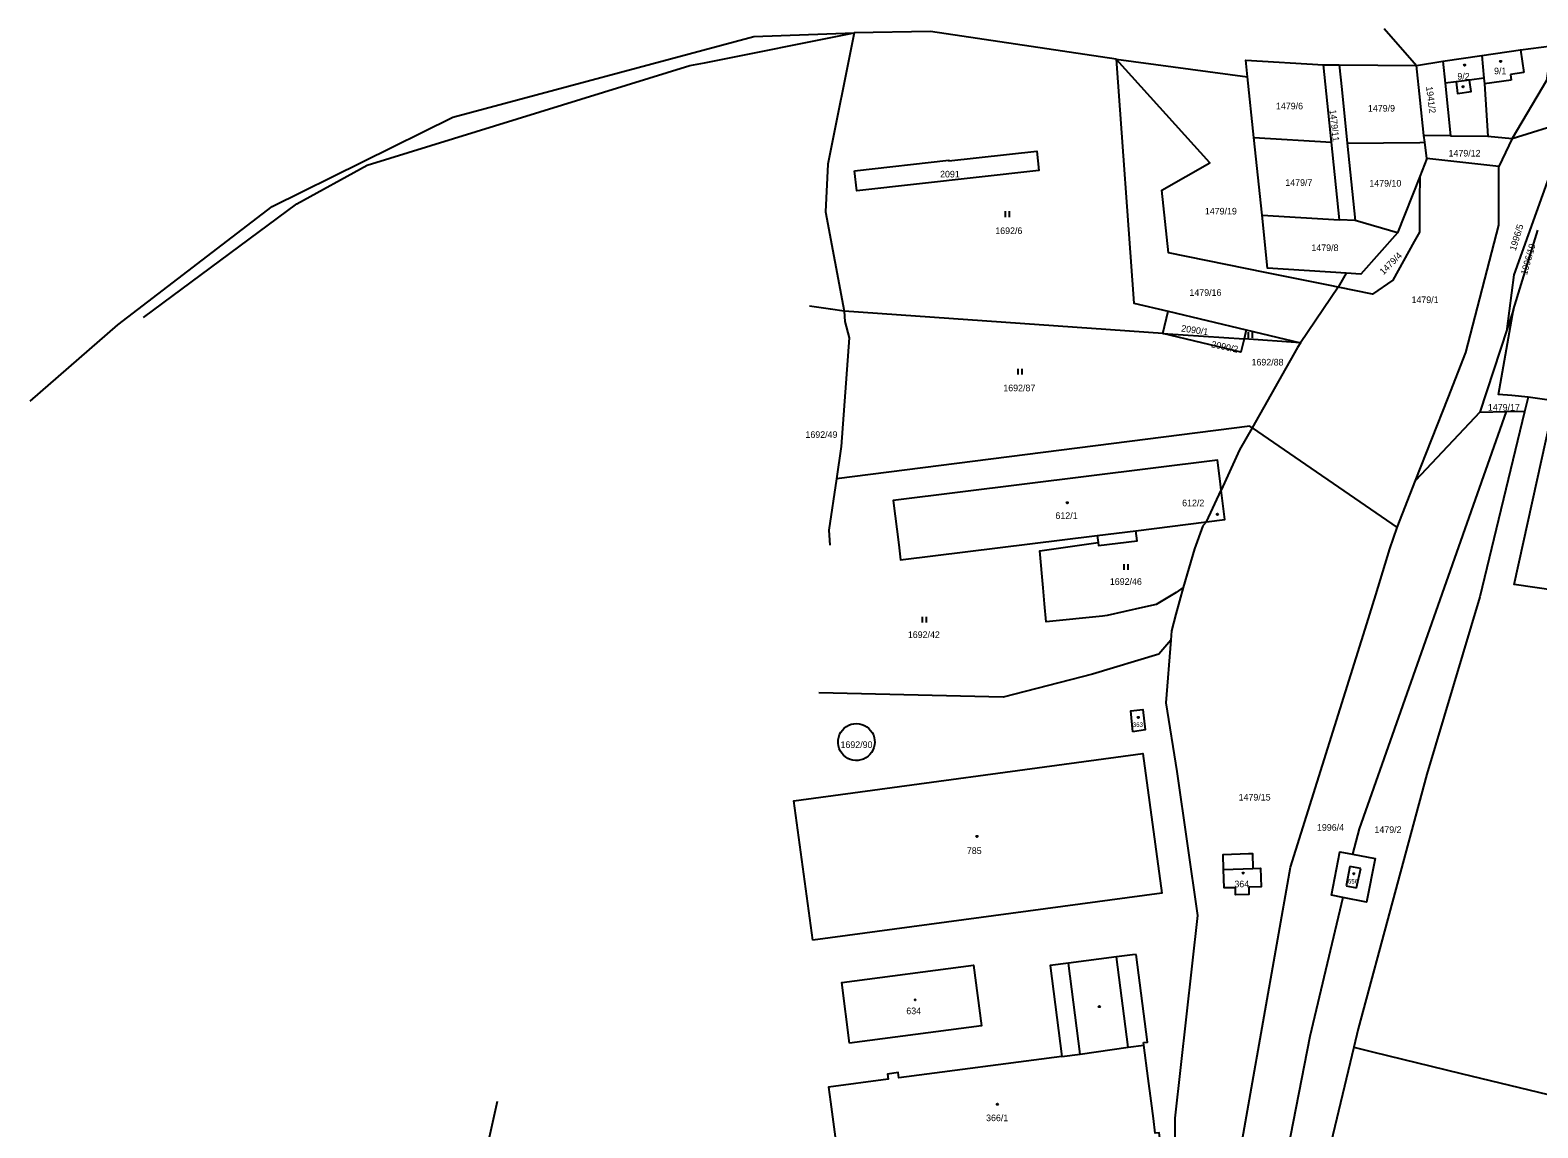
# Model space of a CAD drawing. Extents: x -794765 to -785424, y -1118958 to -1108731.
# Drawn here: x -788665.5 to -788278.3, y -1117100.4 to -1116818.5 of the extents above; entities that cross this region are included whole.
import ezdxf

# ---------------------------------------------------------------- set-up
doc = ezdxf.new("R2010")
doc.units = 0
for name, color, linetype in [('Level 66', 7, 'Continuous'), ('Level 75', 7, 'Continuous'), ('Level 76', 7, 'Continuous'), ('Level 77', 7, 'Continuous'), ('Level 79', 7, 'Continuous')]:
    doc.layers.add(name, color=color, linetype=linetype)

msp = doc.modelspace()

# ---------------------------------------------------------------- linework, layer by layer
at = {"layer": 'Level 66'}
for p, q in [((-788415, -1116866.49), (-788415, -1116864.99)), ((-788414, -1116866.49), (-788414, -1116864.99)), ((-788352.63, -1116897.53), (-788352.63, -1116896.03)), ((-788351.63, -1116897.53), (-788351.63, -1116896.03)), ((-788411.76, -1116906.96), (-788411.76, -1116905.46)), ((-788410.76, -1116906.96), (-788410.76, -1116905.46)), ((-788384.55, -1116957.13), (-788384.55, -1116955.63)), ((-788383.55, -1116957.13), (-788383.55, -1116955.63)), ((-788436.36, -1116970.63), (-788436.36, -1116969.13)), ((-788435.36, -1116970.63), (-788435.36, -1116969.13))]:
    msp.add_line(p, q, dxfattribs=at)
at = {"layer": 'Level 75'}
for p, q in [((-788317.76, -1116818.05), (-788309.48, -1116827.52)), ((-788302.69, -1116826.4), (-788292.73, -1116825.02)), ((-788386.63, -1116825.89), (-788352.86, -1116830.46)), ((-788333.34, -1116827.34), (-788329.35, -1116827.41)), ((-788331.29, -1116847.25), (-788333.34, -1116827.34)), ((-788329.35, -1116827.41), (-788309.48, -1116827.52)), ((-788309.48, -1116827.52), (-788302.69, -1116826.4)), ((-788351.23, -1116846.07), (-788352.86, -1116830.46)), ((-788284.93, -1116846.27), (-788270.62, -1116841.89)), ((-788349.15, -1116865.96), (-788351.23, -1116846.07)), ((-788351.23, -1116846.07), (-788331.29, -1116847.25)), ((-788329.24, -1116867.16), (-788331.29, -1116847.25)), ((-788327.32, -1116847.46), (-788325.2, -1116867.4)), ((-788307.37, -1116847.28), (-788307.58, -1116845.56)), ((-788300.73, -1116845.61), (-788307.58, -1116845.56)), ((-788306.86, -1116851.48), (-788307.37, -1116847.28)), ((-788300.73, -1116845.61), (-788291.15, -1116845.67)), ((-788291.15, -1116845.67), (-788284.93, -1116846.27)), ((-788284.93, -1116846.27), (-788288.33, -1116853.47)), ((-788306.86, -1116851.48), (-788308.66, -1116856.04)), ((-788288.33, -1116853.47), (-788306.86, -1116851.48)), ((-788308.66, -1116856.04), (-788314.38, -1116870.56)), ((-788349.15, -1116865.96), (-788329.24, -1116867.16)), ((-788325.2, -1116867.4), (-788329.24, -1116867.16)), ((-788314.38, -1116870.56), (-788325.2, -1116867.4)), ((-788284.57, -1116890.25), (-788278.3, -1116869.83)), ((-788327.57, -1116880.91), (-788329.59, -1116884.53)), ((-788329.59, -1116884.53), (-788339.25, -1116898.78)), ((-788374.64, -1116896.38), (-788456.49, -1116890.68)), ((-788374.64, -1116896.38), (-788373.27, -1116890.69)), ((-788373.27, -1116890.69), (-788353.2, -1116895.49)), ((-788284.57, -1116890.25), (-788286.19, -1116895.2)), ((-788374.64, -1116896.38), (-788353.75, -1116897.78)), ((-788353.2, -1116895.49), (-788353.75, -1116897.78)), ((-788339.25, -1116898.78), (-788353.75, -1116897.78)), ((-788353.2, -1116895.49), (-788339.25, -1116898.78)), ((-788339.25, -1116898.78), (-788340.06, -1116899.97)), ((-788286.19, -1116895.2), (-788293.21, -1116916.58)), ((-788340.06, -1116899.97), (-788351.7, -1116920.59)), ((-788280.81, -1116912.75), (-788281.72, -1116916.5)), ((-788219.76, -1116921.65), (-788280.81, -1116912.75)), ((-788293.21, -1116916.58), (-788309.73, -1116934.13)), ((-788293.21, -1116916.58), (-788286.44, -1116916.39)), ((-788281.72, -1116916.5), (-788286.44, -1116916.39)), ((-788351.7, -1116920.59), (-788314.48, -1116946.2)), ((-788363.42, -1116944.78), (-788359.67, -1116936.61)), ((-788359.67, -1116936.61), (-788359.89, -1116934.35)), ((-788314.48, -1116946.2), (-788309.73, -1116934.13)), ((-788381.59, -1116947.04), (-788363.42, -1116944.78)), ((-788363.42, -1116944.78), (-788364.33, -1116945.8)), ((-788369.37, -1116961.66), (-788371.22, -1116962.92)), ((-788322.23, -1116970.93), (-788319.9, -1116963.51)), ((-788325.58, -1117079.7), (-788320.78, -1117080.88))]:
    msp.add_line(p, q, dxfattribs=at)
for points in [[(-788665.52, -1116913.8), (-788643.02, -1116894.19), (-788603.36, -1116863.8), (-788557.01, -1116840.86), (-788479.67, -1116820.14), (-788453.87, -1116819.18)], [(-788636.39, -1116892.24), (-788597.01, -1116863.09), (-788578.99, -1116853.18), (-788496.14, -1116827.56), (-788492.3, -1116826.88), (-788453.87, -1116819.18)], [(-788453.87, -1116819.18), (-788460.63, -1116852.93), (-788461.23, -1116865.16), (-788456.49, -1116890.68)], [(-788386.63, -1116825.89), (-788434.34, -1116818.85), (-788453.87, -1116819.18)], [(-788292.73, -1116825.02), (-788282.75, -1116823.53), (-788274.84, -1116822.53), (-788276.12, -1116831.38), (-788284.93, -1116846.27)], [(-788292.73, -1116825.02), (-788292.17, -1116830.8), (-788292.03, -1116832.27), (-788291.15, -1116845.67)], [(-788329.59, -1116884.53), (-788331.7, -1116884.1), (-788348.34, -1116880.7), (-788373.2, -1116875.63), (-788374.9, -1116859.6), (-788362.54, -1116852.57), (-788386.63, -1116825.89)], [(-788386.63, -1116825.89), (-788382.08, -1116888.59), (-788373.27, -1116890.69)], [(-788352.86, -1116830.46), (-788353.31, -1116826.18), (-788333.34, -1116827.34)], [(-788329.35, -1116827.41), (-788328.7, -1116833.74), (-788327.32, -1116847.46)], [(-788307.58, -1116845.56), (-788308.53, -1116836.47), (-788309.48, -1116827.52)], [(-788302.69, -1116826.4), (-788302.1, -1116832.09), (-788300.73, -1116845.61)], [(-788327.32, -1116847.46), (-788308.6, -1116847.29), (-788307.37, -1116847.28)], [(-788453.84, -1116854.6), (-788429.6, -1116851.89), (-788429.57, -1116852.08), (-788407, -1116849.56), (-788406.45, -1116854.49), (-788453.23, -1116859.75), (-788453.84, -1116854.6)], [(-788286.19, -1116895.2), (-788284.39, -1116881.3), (-788274.95, -1116855.05), (-788273.57, -1116849.78)], [(-788308.66, -1116856.04), (-788308.7, -1116862.07), (-788308.75, -1116870.35), (-788310.09, -1116872.78), (-788315.56, -1116882.7), (-788320.81, -1116886.33), (-788329.59, -1116884.53)], [(-788309.73, -1116934.13), (-788301.38, -1116912.93), (-788296.79, -1116901.27), (-788288.35, -1116868.54), (-788288.33, -1116853.47)], [(-788327.57, -1116880.91), (-788347.72, -1116879.64), (-788349.15, -1116865.96)], [(-788314.38, -1116870.56), (-788323.78, -1116881.15), (-788327.57, -1116880.91)], [(-788456.49, -1116890.68), (-788459.97, -1116890.16), (-788465.34, -1116889.35)], [(-788456.49, -1116890.68), (-788456.26, -1116893.3), (-788455.22, -1116897.54), (-788457.2, -1116925.38), (-788458.45, -1116933.71)], [(-788280.81, -1116912.75), (-788285.02, -1116912.36), (-788288.45, -1116912.04), (-788284.57, -1116890.25)], [(-788353.75, -1116897.78), (-788354.57, -1116901.2), (-788374.64, -1116896.38)], [(-788286.44, -1116916.39), (-788324.23, -1117023.59), (-788325.92, -1117030.13)], [(-788281.72, -1116916.5), (-788293.19, -1116964.03), (-788306.8, -1117009.56), (-788324.46, -1117075.03), (-788325.58, -1117079.7)], [(-788160.99, -1116937.11), (-788164.62, -1116978.28), (-788284.44, -1116960.86), (-788274.96, -1116918.14), (-788160.99, -1116937.11)], [(-788351.7, -1116920.59), (-788352.26, -1116920.2), (-788458.45, -1116933.71)], [(-788351.7, -1116920.59), (-788354.93, -1116926.31), (-788359.67, -1116936.61)], [(-788359.89, -1116934.35), (-788360.63, -1116928.9), (-788443.88, -1116939.25), (-788442.46, -1116950.69), (-788441.98, -1116954.55), (-788391.49, -1116948.28), (-788391.25, -1116950.11)], [(-788458.45, -1116933.71), (-788460.41, -1116946.93), (-788460.16, -1116950.78)], [(-788363.42, -1116944.78), (-788358.72, -1116944.2), (-788359.67, -1116936.61)], [(-788391.25, -1116950.11), (-788391.16, -1116950.84), (-788381.24, -1116949.67), (-788381.59, -1116947.04)], [(-788364.33, -1116945.8), (-788366.46, -1116951.67), (-788369.37, -1116961.66)], [(-788319.9, -1116963.51), (-788316.32, -1116951.73), (-788314.48, -1116946.2)], [(-788371.22, -1116962.92), (-788376.33, -1116965.98), (-788379.87, -1116966.79), (-788388.94, -1116968.86), (-788390.17, -1116968.99), (-788404.59, -1116970.47), (-788405.01, -1116965.84), (-788405.39, -1116961.7), (-788406.26, -1116952.23), (-788391.25, -1116950.11)], [(-788369.37, -1116961.66), (-788371.29, -1116968.5), (-788372.43, -1116972.75), (-788372.61, -1116975.15)], [(-788355.85, -1117112.97), (-788341.83, -1117033.48), (-788322.23, -1116970.93)], [(-788372.61, -1116975.15), (-788375.62, -1116978.8), (-788392.69, -1116983.89), (-788415.6, -1116989.83), (-788462.96, -1116988.72)], [(-788372.61, -1116975.15), (-788373.83, -1116991.28), (-788371.03, -1117008.88), (-788365.73, -1117045.9), (-788371.59, -1117097.93), (-788371.59, -1117130.38)], [(-788382.31, -1116998.67), (-788382.89, -1116993.35), (-788379.75, -1116993), (-788379.15, -1116998.2), (-788382.31, -1116998.67)], [(-788453.55, -1117006.07), (-788454.23, -1117005.98), (-788454.9, -1117005.8), (-788455.53, -1117005.52), (-788456.11, -1117005.15), (-788456.64, -1117004.7), (-788457.09, -1117004.19), (-788457.46, -1117003.61), (-788457.75, -1117002.98), (-788457.94, -1117002.32), (-788458.03, -1117001.63), (-788458.04, -1117001.44), (-788458.01, -1117000.75), (-788457.88, -1117000.07), (-788457.65, -1116999.42), (-788457.32, -1116998.81), (-788456.92, -1116998.26), (-788456.44, -1116997.76), (-788455.89, -1116997.35), (-788455.28, -1116997.01), (-788454.64, -1116996.77), (-788453.96, -1116996.62), (-788453.28, -1116996.58), (-788452.59, -1116996.63), (-788451.92, -1116996.79), (-788451.28, -1116997.05), (-788450.68, -1116997.39), (-788450.14, -1116997.82), (-788449.67, -1116998.33), (-788449.28, -1116998.89), (-788448.97, -1116999.51), (-788448.75, -1117000.16), (-788448.64, -1117000.84), (-788448.61, -1117001.38), (-788448.67, -1117002.07), (-788448.83, -1117002.74), (-788449.08, -1117003.38), (-788449.42, -1117003.98), (-788449.85, -1117004.52), (-788450.35, -1117005), (-788450.91, -1117005.39), (-788451.53, -1117005.71), (-788452.18, -1117005.92), (-788452.86, -1117006.05), (-788453.55, -1117006.07)], [(-788464.56, -1117052.22), (-788469.36, -1117016.4), (-788379.74, -1117004.31), (-788374.89, -1117040.12), (-788464.56, -1117052.22)], [(-788352.62, -1117029.97), (-788351.62, -1117029.93), (-788351.49, -1117033.84), (-788349.54, -1117033.77), (-788349.37, -1117038.53), (-788352.58, -1117038.63), (-788352.52, -1117040.48), (-788355.95, -1117040.59), (-788356.01, -1117038.75), (-788358.88, -1117038.81), (-788359.07, -1117034.11), (-788359.18, -1117030.18), (-788352.62, -1117029.97)], [(-788328.38, -1117041.28), (-788331.35, -1117040.69), (-788329.18, -1117029.51), (-788325.92, -1117030.13)], [(-788325.92, -1117030.13), (-788320.09, -1117031.26), (-788322.36, -1117042.47), (-788328.38, -1117041.28)], [(-788328.38, -1117041.28), (-788336.86, -1117076.93), (-788352.61, -1117157.66), (-788354, -1117175.83)], [(-788381.44, -1117055.88), (-788382.45, -1117056.02), (-788386.52, -1117056.54), (-788398.9, -1117058.14), (-788403.61, -1117058.77), (-788400.56, -1117082.11), (-788442.41, -1117087.59), (-788442.59, -1117086.26), (-788445.34, -1117086.66), (-788445.17, -1117087.95), (-788460.49, -1117089.96), (-788459.99, -1117093.74), (-788457.95, -1117109.17), (-788457.73, -1117110.81), (-788459.35, -1117111.02), (-788459.07, -1117113.15), (-788457.45, -1117112.93), (-788456.88, -1117117.22)], [(-788379.58, -1117078.54), (-788378.59, -1117078.41), (-788381.44, -1117055.88)], [(-788455.08, -1117078.71), (-788457.05, -1117063.06), (-788423.25, -1117058.65), (-788421.2, -1117074.21), (-788455.08, -1117078.71)], [(-788377.06, -1117098.05), (-788377.65, -1117093.47), (-788378.39, -1117087.76), (-788379.49, -1117079.23), (-788379.58, -1117078.54)], [(-788325.58, -1117079.7), (-788331.88, -1117106.13), (-788340.36, -1117159.73), (-788336.85, -1117188)], [(-788320.78, -1117080.88), (-788298.06, -1117086.45), (-788260.74, -1117095.5), (-788254.91, -1117096.92), (-788214.58, -1117093.41), (-788166.43, -1117089.58)], [(-788545.61, -1117093.65), (-788556.94, -1117144.89), (-788561.74, -1117170.39), (-788559.26, -1117172.96), (-788408.81, -1117204.79), (-788368.22, -1117208.85)], [(-788371.95, -1117130.3), (-788375.57, -1117101.68), (-788376.57, -1117101.81), (-788377.06, -1117098.05)]]:
    msp.add_lwpolyline(points, dxfattribs=at)
at = {"layer": 'Level 77'}
for p, q in [((-788282.75, -1116823.53), (-788281.95, -1116829.39)), ((-788299.31, -1116831.73), (-788302.1, -1116832.09)), ((-788295.88, -1116831.28), (-788299.31, -1116831.73)), ((-788292.17, -1116830.8), (-788295.88, -1116831.28)), ((-788285.15, -1116831.32), (-788292.03, -1116832.27)), ((-788281.95, -1116829.39), (-788285.35, -1116829.85)), ((-788285.35, -1116829.85), (-788285.15, -1116831.32)), ((-788391.49, -1116948.28), (-788381.59, -1116947.04)), ((-788359.07, -1117034.11), (-788351.49, -1117033.84)), ((-788326.63, -1117033.28), (-788327.54, -1117038.24)), ((-788323.81, -1117033.85), (-788326.63, -1117033.28)), ((-788324.89, -1117038.8), (-788323.81, -1117033.85)), ((-788327.54, -1117038.24), (-788324.89, -1117038.8)), ((-788383.57, -1117079.75), (-788386.52, -1117056.54)), ((-788395.84, -1117081.49), (-788398.9, -1117058.14)), ((-788395.84, -1117081.49), (-788383.57, -1117079.75)), ((-788383.57, -1117079.75), (-788379.49, -1117079.23)), ((-788400.56, -1117082.11), (-788395.84, -1117081.49))]:
    msp.add_line(p, q, dxfattribs=at)
msp.add_lwpolyline([(-788299.31, -1116831.73), (-788298.94, -1116834.72), (-788295.48, -1116834.23), (-788295.88, -1116831.28)], dxfattribs=at)
at = {"layer": 'Level 79'}
for centre in [(-788297.13, -1116827.45), (-788287.87, -1116826.49), (-788297.53, -1116833.02), (-788399.17, -1116939.87), (-788360.6, -1116942.84), (-788380.96, -1116995.01), (-788422.36, -1117025.59), (-788354, -1117034.98), (-788325.58, -1117035.15), (-788438.24, -1117067.55), (-788390.94, -1117069.27), (-788417.12, -1117094.39)]:
    msp.add_circle(centre, 0.175, dxfattribs=at)

# ---------------------------------------------------------------- texts
at = {"layer": 'Level 76'}
for s, height, p in [('9/1', 1.7, (-788289.57, -1116829.8)), ('9/2', 1.7, (-788298.99, -1116831.18)), ('1479/6', 1.7, (-788345.58, -1116838.81)), ('1479/9', 1.7, (-788321.96, -1116839.39)), ('1479/12', 1.7, (-788301.25, -1116850.93)), ('2091', 1.7, (-788431.84, -1116856.31)), ('1479/7', 1.7, (-788343.18, -1116858.47)), ('1479/10', 1.7, (-788321.6, -1116858.65)), ('1479/19', 1.7, (-788363.84, -1116865.82)), ('1692/6', 1.7, (-788417.66, -1116870.85)), ('1479/8', 1.7, (-788336.48, -1116875.22)), ('1479/16', 1.7, (-788367.8, -1116886.72)), ('1479/1', 1.7, (-788310.77, -1116888.58)), ('1692/88', 1.7, (-788351.86, -1116904.61)), ('1692/87', 1.7, (-788415.6, -1116911.22)), ('1479/17', 1.7, (-788291.15, -1116916.21)), ('1692/49', 1.7, (-788466.41, -1116923.2)), ('612/2', 1.7, (-788369.67, -1116940.77)), ('612/1', 1.7, (-788402.21, -1116944.03)), ('1692/46', 1.7, (-788388.24, -1116960.96)), ('1692/42', 1.7, (-788440.11, -1116974.6)), ('363', 1.14, (-788382.35, -1116997.45)), ('1692/90', 1.7, (-788457.41, -1117002.86)), ('1479/15', 1.7, (-788355.17, -1117016.36)), ('1996/4', 1.7, (-788335.05, -1117024.12)), ('1479/2', 1.7, (-788320.28, -1117024.68)), ('785', 1.7, (-788424.96, -1117030.1)), ('364', 1.7, (-788356.26, -1117038.65)), ('656', 1.14, (-788327.11, -1117037.68)), ('634', 1.7, (-788440.51, -1117071.24)), ('366/1', 1.7, (-788420.02, -1117098.72))]:
    msp.add_text(s, height=height, dxfattribs=at).set_placement(p)
for s, rotation, p in [('1941/2', 277, (-788307.04, -1116833.02)), ('1479/11', 276, (-788331.83, -1116838.96)), ('1996/5', 73, (-788284.01, -1116875.27)), ('1479/4', 45, (-788317.97, -1116881.45)), ('1996/19', 74, (-788281.14, -1116881.49)), ('2090/1', 352, (-788369.99, -1116895.86)), ('2090/2', 348, (-788362.31, -1116899.91))]:
    msp.add_text(s, height=1.7, rotation=rotation, dxfattribs=at).set_placement(p)

doc.saveas('drawing.dxf')
